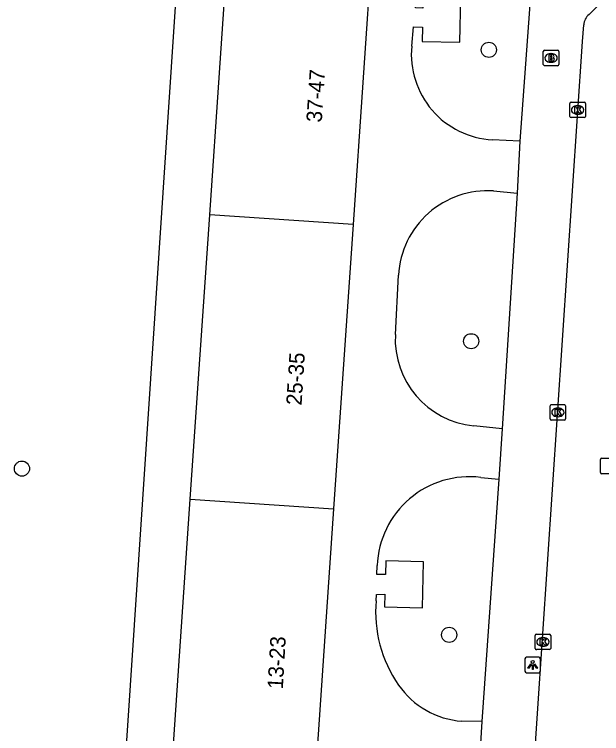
# Model space of a CAD drawing. Extents: x 161848 to 162726, y 385382 to 386521.
# Drawn here: x 162235.98 to 162273.99, y 385418.27 to 385464.81 of the extents above; entities that cross this region are included whole.
import ezdxf

# ---------------------------------------------------------------- set-up
doc = ezdxf.new("R2010")
doc.units = 0
for name, color, linetype in [('IMGEO_Boom', 7, 'Continuous'), ('IMGEO_Brandkraan', 7, 'Continuous'), ('IMGEO_Kolk', 7, 'Continuous'), ('IMGEO_Lichtpunt', 7, 'Continuous'), ('IMGEO_Pand', 7, 'Continuous'), ('IMGEO_Pand_nummerreeks', 7, 'Continuous'), ('IMGEO_Rijbaan_lokaal_open', 7, 'Continuous'), ('IMGEO_Rioolput', 7, 'Continuous'), ('IMGEO_Voetpad_open', 7, 'Continuous')]:
    doc.layers.add(name, color=color, linetype=linetype)

msp = doc.modelspace()

# ---------------------------------------------------------------- linework, layer by layer
at = {"layer": 'IMGEO_Boom'}
for centre in [(162266.695, 385462.519), (162265.549, 385443.66), (162236.471, 385435.417), (162264.124, 385424.661)]:
    msp.add_circle(centre, 0.489, dxfattribs=at)
at = {"layer": 'IMGEO_Brandkraan'}
for p, q in [((162270.218, 385461.567), (162270.218, 385462.419)), ((162270.293, 385462.493), (162271.145, 385462.493)), ((162271.219, 385462.419), (162271.219, 385461.567)), ((162270.706, 385462.273), (162270.731, 385462.273)), ((162271.145, 385461.493), (162270.293, 385461.493)), ((162270.729, 385461.713), (162270.704, 385461.713))]:
    msp.add_line(p, q, dxfattribs=at)
for points in [[(162270.218, 385461.567), (162270.218, 385462.419)], [(162270.293, 385462.493), (162271.145, 385462.493)], [(162271.219, 385462.419), (162271.219, 385461.567)], [(162270.566, 385462.193), (162270.566, 385461.793), (162270.779, 385461.793)], [(162270.797, 385462.193), (162270.566, 385462.193)], [(162270.745, 385462.112), (162270.691, 385462.112), (162270.691, 385462.036)], [(162270.691, 385462.036), (162270.744, 385462.036)], [(162270.753, 385461.96), (162270.691, 385461.96), (162270.691, 385461.879)], [(162271.145, 385461.493), (162270.293, 385461.493)], [(162270.691, 385461.879), (162270.753, 385461.879)]]:
    msp.add_lwpolyline(points, dxfattribs=at)
for centre, radius, start, end in [((162270.295, 385462.417), 0.0765, 91.552, 178.448), ((162270.295, 385462.417), 0.0765, 91.552, 178.448), ((162271.143, 385462.417), 0.0765, 1.552, 88.448), ((162271.143, 385462.417), 0.0765, 1.552, 88.448), ((162270.746, 385462.074), 0.0379, 267.8285, 90.9355), ((162270.754, 385461.919), 0.0404, 269.8759, 90.5077), ((162270.801, 385462.048), 0.145, 59.4692, 91.5367), ((162270.826, 385462.095), 0.0922, 285.5137, 58.1501), ((162270.831, 385461.903), 0.105, 301.3115, 78.989), ((162270.295, 385461.569), 0.0765, 181.552, 268.448), ((162270.295, 385461.569), 0.0765, 181.552, 268.448), ((162270.785, 385462.044), 0.251, 268.6676, 293.5347), ((162271.143, 385461.569), 0.0765, 271.552, 358.448), ((162271.143, 385461.569), 0.0765, 271.552, 358.448)]:
    msp.add_arc(centre, radius, start, end, dxfattribs=at)
for centre, major_axis, ratio, start_param, end_param in [((162270.705, 385461.993), (-0.387, 0.002), 0.722429, 4.712389, 7.853982), ((162270.73, 385461.993), (-0.39, 0.002), 0.717154, 1.570796, 4.712389)]:
    msp.add_ellipse(centre, major_axis=major_axis, ratio=ratio, start_param=start_param, end_param=end_param, dxfattribs=at)
at = {"layer": 'IMGEO_Kolk'}
for p, q in [((162272.013, 385459.129), (162272.865, 385459.129)), ((162271.938, 385458.203), (162271.938, 385459.055)), ((162272.426, 385458.909), (162272.451, 385458.909)), ((162272.939, 385459.055), (162272.939, 385458.203)), ((162272.449, 385458.349), (162272.424, 385458.349)), ((162272.865, 385458.129), (162272.013, 385458.129)), ((162270.66, 385438.629), (162270.66, 385439.481)), ((162270.735, 385439.555), (162271.587, 385439.555)), ((162271.148, 385439.335), (162271.173, 385439.335)), ((162271.661, 385439.481), (162271.661, 385438.629)), ((162271.171, 385438.775), (162271.146, 385438.775)), ((162271.587, 385438.555), (162270.735, 385438.555)), ((162269.768, 385424.7), (162270.62, 385424.7)), ((162269.693, 385423.774), (162269.693, 385424.626)), ((162270.181, 385424.48), (162270.206, 385424.48)), ((162270.694, 385424.626), (162270.694, 385423.774)), ((162270.204, 385423.92), (162270.179, 385423.92)), ((162270.62, 385423.7), (162269.768, 385423.7))]:
    msp.add_line(p, q, dxfattribs=at)
for points in [[(162272.013, 385459.129), (162272.865, 385459.129)], [(162271.938, 385458.203), (162271.938, 385459.055)], [(162272.259, 385458.829), (162272.382, 385458.829), (162272.382, 385458.678), (162272.512, 385458.829), (162272.676, 385458.829), (162272.53, 385458.678), (162272.683, 385458.429), (162272.531, 385458.429), (162272.446, 385458.593), (162272.382, 385458.526), (162272.382, 385458.429), (162272.259, 385458.429), (162272.259, 385458.829)], [(162272.939, 385459.055), (162272.939, 385458.203)], [(162272.865, 385458.129), (162272.013, 385458.129)], [(162270.66, 385438.629), (162270.66, 385439.481)], [(162270.735, 385439.555), (162271.587, 385439.555)], [(162270.981, 385439.255), (162271.104, 385439.255), (162271.104, 385439.104), (162271.234, 385439.255), (162271.398, 385439.255), (162271.252, 385439.104), (162271.405, 385438.855), (162271.253, 385438.855), (162271.168, 385439.019), (162271.104, 385438.952), (162271.104, 385438.855), (162270.981, 385438.855), (162270.981, 385439.255)], [(162271.661, 385439.481), (162271.661, 385438.629)], [(162271.587, 385438.555), (162270.735, 385438.555)], [(162269.768, 385424.7), (162270.62, 385424.7)], [(162269.693, 385423.774), (162269.693, 385424.626)], [(162270.014, 385424.4), (162270.137, 385424.4), (162270.137, 385424.249), (162270.267, 385424.4), (162270.431, 385424.4), (162270.285, 385424.249), (162270.438, 385424), (162270.286, 385424), (162270.201, 385424.164), (162270.137, 385424.097), (162270.137, 385424), (162270.014, 385424), (162270.014, 385424.4)], [(162270.694, 385424.626), (162270.694, 385423.774)], [(162270.62, 385423.7), (162269.768, 385423.7)]]:
    msp.add_lwpolyline(points, dxfattribs=at)
for centre, start, end in [((162272.015, 385459.053), 91.552, 178.448), ((162272.015, 385459.053), 91.552, 178.448), ((162272.863, 385459.053), 1.552, 88.448), ((162272.863, 385459.053), 1.552, 88.448), ((162272.015, 385458.205), 181.552, 268.448), ((162272.015, 385458.205), 181.552, 268.448), ((162272.863, 385458.205), 271.552, 358.448), ((162272.863, 385458.205), 271.552, 358.448), ((162270.737, 385439.479), 91.552, 178.448), ((162270.737, 385439.479), 91.552, 178.448), ((162271.585, 385439.479), 1.552, 88.448), ((162271.585, 385439.479), 1.552, 88.448), ((162270.737, 385438.631), 181.552, 268.448), ((162270.737, 385438.631), 181.552, 268.448), ((162271.585, 385438.631), 271.552, 358.448), ((162271.585, 385438.631), 271.552, 358.448), ((162269.77, 385424.624), 91.552, 178.448), ((162269.77, 385424.624), 91.552, 178.448), ((162270.618, 385424.624), 1.552, 88.448), ((162270.618, 385424.624), 1.552, 88.448), ((162269.77, 385423.776), 181.552, 268.448), ((162269.77, 385423.776), 181.552, 268.448), ((162270.618, 385423.776), 271.552, 358.448), ((162270.618, 385423.776), 271.552, 358.448)]:
    msp.add_arc(centre, 0.0765, start, end, dxfattribs=at)
for centre, major_axis, ratio, start_param, end_param in [((162272.425, 385458.629), (-0.387, 0.002), 0.722429, 4.712389, 7.853982), ((162272.45, 385458.629), (-0.39, 0.002), 0.717154, 1.570796, 4.712389), ((162271.147, 385439.055), (-0.387, 0.002), 0.722429, 4.712389, 7.853982), ((162271.172, 385439.055), (-0.39, 0.002), 0.717154, 1.570796, 4.712389), ((162270.18, 385424.2), (-0.387, 0.002), 0.722429, 4.712389, 7.853982), ((162270.205, 385424.2), (-0.39, 0.002), 0.717154, 1.570796, 4.712389)]:
    msp.add_ellipse(centre, major_axis=major_axis, ratio=ratio, start_param=start_param, end_param=end_param, dxfattribs=at)
at = {"layer": 'IMGEO_Lichtpunt'}
for p, q in [((162269.032, 385423.112), (162269.032, 385422.305)), ((162269.032, 385423.112), (162269.032, 385422.305)), ((162269.934, 385423.207), (162269.126, 385423.207)), ((162269.934, 385423.207), (162269.126, 385423.207)), ((162270.028, 385422.305), (162270.028, 385423.112)), ((162270.028, 385422.305), (162270.028, 385423.112)), ((162269.126, 385422.211), (162269.934, 385422.211)), ((162269.126, 385422.211), (162269.934, 385422.211))]:
    msp.add_line(p, q, dxfattribs=at)
for points in [[(162269.406, 385422.776), (162269.445, 385422.748), (162269.257, 385422.486), (162269.219, 385422.513), (162269.406, 385422.776)], [(162269.508, 385422.728), (162269.555, 385422.728), (162269.555, 385422.406), (162269.508, 385422.406), (162269.508, 385422.728)], [(162269.618, 385422.748), (162269.656, 385422.775), (162269.843, 385422.513), (162269.804, 385422.485), (162269.618, 385422.748)]]:
    msp.add_lwpolyline(points, dxfattribs=at)
msp.add_circle((162269.531, 385422.91), 0.0994, dxfattribs=at)
for centre, start, end in [((162269.126, 385423.112), 90, 180), ((162269.126, 385423.112), 90, 180), ((162269.934, 385423.112), 0, 90), ((162269.934, 385423.112), 0, 90), ((162269.126, 385422.305), 180, 270), ((162269.126, 385422.305), 180, 270), ((162269.934, 385422.305), 270, 0), ((162269.934, 385422.305), 270, 360)]:
    msp.add_arc(centre, 0.0946, start, end, dxfattribs=at)
at = {"layer": 'IMGEO_Pand'}
for points in [[(162248.624, 385451.841), (162249.879, 385470.239)], [(162259.156, 385469.606), (162257.902, 385451.209)], [(162247.369, 385433.444), (162248.624, 385451.841)], [(162257.902, 385451.209), (162248.624, 385451.841)], [(162257.902, 385451.209), (162256.647, 385432.811)], [(162246.114, 385415.046), (162247.369, 385433.444)], [(162247.369, 385433.444), (162256.647, 385432.811)], [(162256.647, 385432.811), (162255.393, 385414.414)]]:
    msp.add_lwpolyline(points, dxfattribs=at)
at = {"layer": 'IMGEO_Rijbaan_lokaal_open'}
for points in [[(162273.176, 385464.812), (162273.988, 385465.604)], [(162268.862, 385405.077), (162272.75, 385463.047), (162272.835, 385464.128)]]:
    msp.add_lwpolyline(points, dxfattribs=at)
msp.add_arc((162273.826, 385464.061), 0.993, 130.8692, 176.1348, dxfattribs=at)
at = {"layer": 'IMGEO_Rioolput'}
for p, q in [((162273.917, 385435.163), (162273.917, 385436.015)), ((162273.992, 385436.089), (162274.844, 385436.089)), ((162274.844, 385435.089), (162273.992, 385435.089))]:
    msp.add_line(p, q, dxfattribs=at)
for points in [[(162273.917, 385435.163), (162273.917, 385436.015)], [(162273.992, 385436.089), (162274.844, 385436.089)], [(162274.844, 385435.089), (162273.992, 385435.089)]]:
    msp.add_lwpolyline(points, dxfattribs=at)
for centre, start, end in [((162273.994, 385436.013), 91.552, 178.448), ((162273.994, 385436.013), 91.552, 178.448), ((162273.994, 385435.165), 181.552, 268.448), ((162273.994, 385435.165), 181.552, 268.448)]:
    msp.add_arc(centre, 0.0765, start, end, dxfattribs=at)
at = {"layer": 'IMGEO_Voetpad_open'}
for points in [[(162262.479, 385534.283), (162261.965, 385526.444), (162250.499, 385527.157), (162241.486, 385391.457)], [(162269.753, 385471.068), (162268.704, 385456.607)], [(162261.7, 385462.758), (162261.82, 385464.01), (162262.39, 385463.989), (162262.368, 385463.068), (162264.819, 385463.01), (162264.889, 385465.975), (162262.439, 385466.033), (162262.419, 385465.208), (162261.937, 385465.228), (162262.029, 385466.193)], [(162268.704, 385456.607), (162266.924, 385456.7)], [(162268.704, 385456.607), (162268.527, 385453.246)], [(162266.997, 385453.383), (162268.527, 385453.246)], [(162268.527, 385453.246), (162267.563, 385437.996)], [(162260.642, 385444.097), (162260.848, 385447.937)], [(162267.563, 385437.996), (162265.711, 385438.182)], [(162267.563, 385437.996), (162267.337, 385434.743)], [(162266.167, 385434.846), (162267.337, 385434.743)], [(162267.337, 385434.743), (162266.246, 385419.052)], [(162259.398, 385426.87), (162259.41, 385427.271), (162259.968, 385427.283), (162259.949, 385426.468), (162262.397, 385426.41), (162262.468, 385429.388), (162260.02, 385429.446), (162259.999, 385428.573), (162259.45, 385428.574), (162259.467, 385429.143)], [(162266.246, 385419.052), (162264.948, 385419.073)], [(162266.246, 385419.052), (162266.047, 385415.86)]]:
    msp.add_lwpolyline(points, dxfattribs=at)
for centre, radius, start, end in [((162267.21, 385462.228), 5.535, 174.5052, 267.0392), ((162266.607, 385447.629), 5.767, 86.1251, 176.9358), ((162266.276, 385443.795), 5.642, 176.936, 264.2555), ((162265.435, 385428.918), 5.973, 82.9641, 177.8444), ((162267.609, 385426.129), 8.244, 174.8464, 214.8948), ((162265.34, 385424.524), 5.465, 214.6978, 265.8847)]:
    msp.add_arc(centre, radius, start, end, dxfattribs=at)

# ---------------------------------------------------------------- texts
at = {"layer": 'IMGEO_Pand_nummerreeks'}
for s, rotation, p in [('37-47', 86.1936, (162255.873, 385457.802)), ('25-35', 86.3012, (162254.569, 385439.488)), ('13-23', 86.6872, (162253.356, 385421.123))]:
    msp.add_text(s, height=1, rotation=rotation, dxfattribs=at).set_placement(p)

doc.saveas('drawing.dxf')
